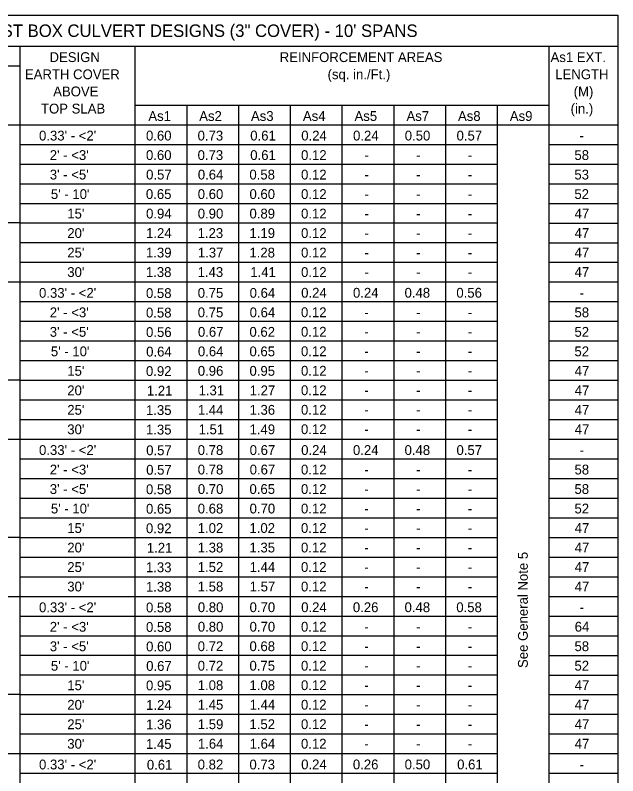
# Model space of a CAD drawing. Extents: x 10351.18 to 10353.4, y 76371.55 to 76372.62.
# Drawn here: x 10351.4001 to 10351.7867, y 76372.0471 to 76372.5347 of the extents above; entities that cross this region are included whole.
import ezdxf

# ---------------------------------------------------------------- set-up
doc = ezdxf.new("R2010")
doc.units = 0
doc.layers.add('AdhocPoint_dp', color=7, linetype='Continuous')
doc.layers.add('PlotBorder_dp', color=7, linetype='Continuous')

msp = doc.modelspace()

# ---------------------------------------------------------------- linework, layer by layer
at = {"layer": 'PlotBorder_dp'}
for p, q in [((10351.19191, 76372.53475), (10351.78665, 76372.53475)), ((10351.78665, 76372.53475), (10351.78665, 76371.85973)), ((10351.19191, 76372.51488), (10351.78665, 76372.51488)), ((10351.40299, 76372.51488), (10351.40299, 76371.85973)), ((10351.47687, 76372.51488), (10351.47687, 76371.85973)), ((10351.74246, 76372.51488), (10351.74246, 76371.85973)), ((10351.26055, 76372.50228), (10351.40299, 76372.50228)), ((10351.47687, 76372.47713), (10351.74246, 76372.47713)), ((10351.51007, 76372.47713), (10351.51007, 76371.85973)), ((10351.54327, 76372.47713), (10351.54327, 76371.85973)), ((10351.57647, 76372.47713), (10351.57647, 76371.85973)), ((10351.60967, 76372.47713), (10351.60967, 76371.85973)), ((10351.64287, 76372.47713), (10351.64287, 76371.85973)), ((10351.64287, 76372.47713), (10351.64287, 76371.85973)), ((10351.67606, 76372.47713), (10351.67606, 76371.85973)), ((10351.70926, 76372.47713), (10351.70926, 76371.85973)), ((10351.19191, 76372.46453), (10351.78665, 76372.46453)), ((10351.40299, 76372.45193), (10351.70926, 76372.45193)), ((10351.74246, 76372.45191), (10351.78665, 76372.45191)), ((10351.40299, 76372.43933), (10351.70926, 76372.43933)), ((10351.74246, 76372.43931), (10351.78665, 76372.43931)), ((10351.40299, 76372.42673), (10351.70926, 76372.42673)), ((10351.74246, 76372.42671), (10351.78665, 76372.42671)), ((10351.40299, 76372.41413), (10351.70926, 76372.41413)), ((10351.74246, 76372.41411), (10351.78665, 76372.41411)), ((10351.40299, 76372.40153), (10351.26055, 76372.40153)), ((10351.40299, 76372.40153), (10351.70926, 76372.40153)), ((10351.74246, 76372.40151), (10351.78665, 76372.40151)), ((10351.40299, 76372.38893), (10351.70926, 76372.38893)), ((10351.74246, 76372.38891), (10351.78665, 76372.38891)), ((10351.40299, 76372.37633), (10351.70926, 76372.37633)), ((10351.74246, 76372.37631), (10351.78665, 76372.37631)), ((10351.19191, 76372.36373), (10351.70926, 76372.36373)), ((10351.40362, 76372.36371), (10351.4758, 76372.36371)), ((10351.74246, 76372.36371), (10351.78665, 76372.36371)), ((10351.40299, 76372.35113), (10351.70926, 76372.35113)), ((10351.74246, 76372.35111), (10351.78665, 76372.35111)), ((10351.40299, 76372.33853), (10351.70926, 76372.33853)), ((10351.74246, 76372.33851), (10351.78665, 76372.33851)), ((10351.40299, 76372.32593), (10351.70926, 76372.32593)), ((10351.74246, 76372.32591), (10351.78665, 76372.32591)), ((10351.40299, 76372.31333), (10351.70926, 76372.31333)), ((10351.74246, 76372.31331), (10351.78665, 76372.31331)), ((10351.40299, 76372.30073), (10351.26055, 76372.30073)), ((10351.40299, 76372.30073), (10351.70926, 76372.30073)), ((10351.74246, 76372.30071), (10351.78665, 76372.30071)), ((10351.40299, 76372.28813), (10351.70926, 76372.28813)), ((10351.74246, 76372.28811), (10351.78665, 76372.28811)), ((10351.40299, 76372.27553), (10351.70926, 76372.27553)), ((10351.40362, 76372.27551), (10351.4758, 76372.27551)), ((10351.74246, 76372.27551), (10351.78665, 76372.27551)), ((10351.19191, 76372.26293), (10351.70926, 76372.26293)), ((10351.74246, 76372.26291), (10351.78665, 76372.26291)), ((10351.40299, 76372.25033), (10351.70926, 76372.25033)), ((10351.74246, 76372.25031), (10351.78665, 76372.25031)), ((10351.40299, 76372.23773), (10351.70926, 76372.23773)), ((10351.74246, 76372.23771), (10351.78665, 76372.23771)), ((10351.40299, 76372.22513), (10351.70926, 76372.22513)), ((10351.74246, 76372.22511), (10351.78665, 76372.22511)), ((10351.40299, 76372.21253), (10351.70926, 76372.21253)), ((10351.74246, 76372.21251), (10351.78665, 76372.21251)), ((10351.40299, 76372.19993), (10351.26055, 76372.19993)), ((10351.40299, 76372.19993), (10351.70926, 76372.19993)), ((10351.74246, 76372.19991), (10351.78665, 76372.19991)), ((10351.40299, 76372.18733), (10351.70926, 76372.18733)), ((10351.74246, 76372.18731), (10351.78665, 76372.18731)), ((10351.40299, 76372.17473), (10351.70926, 76372.17473)), ((10351.74246, 76372.17471), (10351.78665, 76372.17471)), ((10351.19191, 76372.16213), (10351.70926, 76372.16213)), ((10351.40362, 76372.16211), (10351.4758, 76372.16211)), ((10351.74246, 76372.16211), (10351.78665, 76372.16211)), ((10351.40299, 76372.14953), (10351.70926, 76372.14953)), ((10351.74246, 76372.14951), (10351.78665, 76372.14951)), ((10351.40299, 76372.13693), (10351.70926, 76372.13693)), ((10351.74246, 76372.13691), (10351.78665, 76372.13691)), ((10351.40299, 76372.12433), (10351.70926, 76372.12433)), ((10351.74246, 76372.12431), (10351.78665, 76372.12431)), ((10351.40299, 76372.11173), (10351.70926, 76372.11173)), ((10351.74246, 76372.11171), (10351.78665, 76372.11171)), ((10351.40299, 76372.09913), (10351.26055, 76372.09913)), ((10351.40299, 76372.09913), (10351.70926, 76372.09913)), ((10351.74246, 76372.09911), (10351.78665, 76372.09911)), ((10351.40299, 76372.08653), (10351.70926, 76372.08653)), ((10351.74246, 76372.08651), (10351.78665, 76372.08651)), ((10351.40299, 76372.07393), (10351.70926, 76372.07393)), ((10351.74246, 76372.07391), (10351.78665, 76372.07391)), ((10351.19191, 76372.06133), (10351.70926, 76372.06133)), ((10351.40362, 76372.06131), (10351.4758, 76372.06131)), ((10351.74246, 76372.06131), (10351.78665, 76372.06131)), ((10351.40299, 76372.04873), (10351.70926, 76372.04873)), ((10351.74246, 76372.04871), (10351.78665, 76372.04871))]:
    msp.add_line(p, q, dxfattribs=at)

# ---------------------------------------------------------------- texts
at = {"layer": 'AdhocPoint_dp'}
for s, height, p in [('TABLE 14 - STANDARD PRECAST BOX CULVERT DESIGNS (3" COVER) - 10\' SPANS', 0.008, (10351.23445, 76372.52081)), ('As1', 0.0063, (10351.48549, 76372.46696)), ('As2', 0.0063, (10351.51812, 76372.46696)), ('As3', 0.0063, (10351.55132, 76372.46696)), ('As4', 0.0063, (10351.58465, 76372.46696)), ('As5', 0.0063, (10351.61775, 76372.46696)), ('As7', 0.0063, (10351.65109, 76372.46696)), ('As8', 0.0063, (10351.68413, 76372.46696)), ('As9', 0.0063, (10351.71738, 76372.46696))]:
    msp.add_text(s, height=height, dxfattribs=at).set_placement(p)
msp.add_text('See General Note 5', height=0.0063, rotation=90, dxfattribs=at).set_placement((10351.72891, 76372.11621))
at = {"layer": 'PlotBorder_dp'}
for s, p in [('DESIGN', (10351.42209, 76372.50472)), ('REINFORCEMENT AREAS', (10351.56977, 76372.50472)), ('EARTH COVER', (10351.4063, 76372.49372)), ('(sq. in./Ft.)', (10351.60047, 76372.49372)), ('ABOVE', (10351.42444, 76372.48272)), ('TOP SLAB', (10351.41661, 76372.47172)), ("0.33' - <2'", (10351.41535, 76372.45441)), ('0.60', (10351.48397, 76372.45441)), ('0.73', (10351.51709, 76372.45441)), ('0.61', (10351.55086, 76372.45441)), ('0.24', (10351.58358, 76372.45441)), ('0.24', (10351.61681, 76372.45441)), ('0.50', (10351.64997, 76372.45441)), ('0.57', (10351.68322, 76372.45441)), ("2' - <3'", (10351.42225, 76372.44191)), ('0.60', (10351.48397, 76372.44191)), ('0.73', (10351.51709, 76372.44191)), ('0.61', (10351.55086, 76372.44191)), ('0.12', (10351.58345, 76372.44191)), ('-', (10351.62409, 76372.44191)), ('-', (10351.6573, 76372.44191)), ('-', (10351.69048, 76372.44191)), ("3' - <5'", (10351.42225, 76372.42941)), ('0.57', (10351.48404, 76372.42941)), ('0.64', (10351.51722, 76372.42941)), ('0.58', (10351.55031, 76372.42941)), ('0.12', (10351.58345, 76372.42941)), ('-', (10351.62409, 76372.42941)), ('-', (10351.6573, 76372.42941)), ('-', (10351.69048, 76372.42941)), ("5' - 10'", (10351.42296, 76372.41691)), ('0.65', (10351.48392, 76372.41691)), ('0.60', (10351.51717, 76372.41691)), ('0.60', (10351.55037, 76372.41691)), ('0.12', (10351.58345, 76372.41691)), ('-', (10351.62409, 76372.41691)), ('-', (10351.6573, 76372.41691)), ('-', (10351.69048, 76372.41691)), ("15'", (10351.43348, 76372.40441)), ('0.94', (10351.48402, 76372.40441)), ('0.90', (10351.51717, 76372.40441)), ('0.89', (10351.55036, 76372.40441)), ('0.12', (10351.58345, 76372.40441)), ('-', (10351.62409, 76372.40441)), ('-', (10351.6573, 76372.40441)), ('-', (10351.69048, 76372.40441)), ("20'", (10351.43348, 76372.39191)), ('1.24', (10351.48402, 76372.39191)), ('1.23', (10351.51709, 76372.39191)), ('1.19', (10351.55036, 76372.39191)), ('0.12', (10351.58345, 76372.39191)), ('-', (10351.62409, 76372.39191)), ('-', (10351.6573, 76372.39191)), ('-', (10351.69048, 76372.39191)), ("25'", (10351.43348, 76372.37941)), ('1.39', (10351.48396, 76372.37941)), ('1.37', (10351.51724, 76372.37941)), ('1.28', (10351.55031, 76372.37941)), ('0.12', (10351.58345, 76372.37941)), ('-', (10351.62409, 76372.37941)), ('-', (10351.6573, 76372.37941)), ('-', (10351.69048, 76372.37941)), ("30'", (10351.43348, 76372.36691)), ('1.38', (10351.48391, 76372.36691)), ('1.43', (10351.51709, 76372.36691)), ('1.41', (10351.55086, 76372.36691)), ('0.12', (10351.58345, 76372.36691)), ('-', (10351.62409, 76372.36691)), ('-', (10351.6573, 76372.36691)), ('-', (10351.69048, 76372.36691)), ("0.33' - <2'", (10351.41535, 76372.35357)), ('0.58', (10351.48397, 76372.35342)), ('0.75', (10351.51717, 76372.35357)), ('0.64', (10351.55047, 76372.35357)), ('0.24', (10351.58352, 76372.35363)), ('0.24', (10351.61676, 76372.35363)), ('0.48', (10351.64986, 76372.35363)), ('0.56', (10351.68309, 76372.35363)), ('-', (10351.76219, 76372.35357)), ("2' - <3'", (10351.42225, 76372.34107)), ('0.58', (10351.48397, 76372.34092)), ('0.75', (10351.51717, 76372.34107)), ('0.64', (10351.55047, 76372.34107)), ('0.12', (10351.5834, 76372.34113)), ('58', (10351.75887, 76372.34107)), ('-', (10351.62403, 76372.34113)), ('-', (10351.65724, 76372.34113)), ('-', (10351.69043, 76372.34113)), ("3' - <5'", (10351.42225, 76372.32857)), ('0.56', (10351.48401, 76372.32842)), ('0.67', (10351.51729, 76372.32857)), ('0.62', (10351.55035, 76372.32857)), ('0.12', (10351.5834, 76372.32863)), ('-', (10351.62403, 76372.32863)), ('-', (10351.65724, 76372.32863)), ('-', (10351.69043, 76372.32863)), ('52', (10351.75885, 76372.32857)), ("5' - 10'", (10351.42296, 76372.31607)), ('0.64', (10351.48407, 76372.31592)), ('0.64', (10351.51727, 76372.31607)), ('0.65', (10351.55037, 76372.31607)), ('0.12', (10351.5834, 76372.31613)), ('52', (10351.75885, 76372.31607)), ('-', (10351.62403, 76372.31613)), ('-', (10351.65724, 76372.31613)), ('-', (10351.69043, 76372.31613)), ("15'", (10351.43348, 76372.30357)), ('0.92', (10351.48395, 76372.30342)), ('0.96', (10351.51721, 76372.30357)), ('0.95', (10351.55037, 76372.30357)), ('0.12', (10351.5834, 76372.30363)), ('-', (10351.62403, 76372.30363)), ('-', (10351.65724, 76372.30363)), ('-', (10351.69043, 76372.30363)), ('47', (10351.759, 76372.30357)), ("20'", (10351.43348, 76372.29107)), ('1.21', (10351.48452, 76372.29092)), ('1.31', (10351.51771, 76372.29107)), ('1.27', (10351.55049, 76372.29107)), ('0.12', (10351.5834, 76372.29113)), ('47', (10351.759, 76372.29107)), ('-', (10351.62403, 76372.29113)), ('-', (10351.65724, 76372.29113)), ('-', (10351.69043, 76372.29113)), ("25'", (10351.43348, 76372.27857)), ('1.35', (10351.48397, 76372.27842)), ('1.44', (10351.51727, 76372.27857)), ('1.36', (10351.55041, 76372.27857)), ('0.12', (10351.5834, 76372.27863)), ('47', (10351.759, 76372.27857)), ('-', (10351.62403, 76372.27863)), ('-', (10351.65724, 76372.27863)), ('-', (10351.69043, 76372.27863)), ("30'", (10351.43348, 76372.26607)), ('1.35', (10351.48397, 76372.26592)), ('1.51', (10351.51771, 76372.26607)), ('1.49', (10351.55041, 76372.26607)), ('0.12', (10351.5834, 76372.26613)), ('47', (10351.759, 76372.26607)), ('-', (10351.62403, 76372.26613)), ('-', (10351.65724, 76372.26613)), ('-', (10351.69043, 76372.26613)), ("0.33' - <2'", (10351.41535, 76372.25279)), ('0.57', (10351.48409, 76372.25264)), ('0.78', (10351.51716, 76372.25279)), ('0.67', (10351.55049, 76372.25279)), ('0.24', (10351.58352, 76372.25279)), ('0.24', (10351.61676, 76372.25279)), ('0.48', (10351.64986, 76372.25279)), ('0.57', (10351.68317, 76372.25279)), ('-', (10351.76219, 76372.25279)), ("2' - <3'", (10351.42225, 76372.24029)), ('0.57', (10351.48409, 76372.24014)), ('0.78', (10351.51716, 76372.24029)), ('0.67', (10351.55049, 76372.24029)), ('0.12', (10351.5834, 76372.24029)), ('-', (10351.62403, 76372.24029)), ('-', (10351.65724, 76372.24029)), ('-', (10351.69043, 76372.24029)), ('58', (10351.75887, 76372.24029)), ("3' - <5'", (10351.42225, 76372.22779)), ('0.58', (10351.48397, 76372.22764)), ('0.70', (10351.51722, 76372.22779)), ('0.65', (10351.55037, 76372.22779)), ('0.12', (10351.5834, 76372.22779)), ('58', (10351.75887, 76372.22779)), ('-', (10351.62403, 76372.22779)), ('-', (10351.65724, 76372.22779)), ('-', (10351.69043, 76372.22779)), ("5' - 10'", (10351.42296, 76372.21529)), ('0.65', (10351.48397, 76372.21514)), ('0.68', (10351.51716, 76372.21529)), ('0.70', (10351.55043, 76372.21529)), ('0.12', (10351.5834, 76372.21529)), ('52', (10351.75885, 76372.21529)), ('-', (10351.62403, 76372.21529)), ('-', (10351.65724, 76372.21529)), ('-', (10351.69043, 76372.21529)), ("15'", (10351.43348, 76372.20279)), ('0.92', (10351.48395, 76372.20264)), ('1.02', (10351.51715, 76372.20279)), ('1.02', (10351.55035, 76372.20279)), ('0.12', (10351.5834, 76372.20279)), ('47', (10351.759, 76372.20279)), ('-', (10351.62403, 76372.20279)), ('-', (10351.65724, 76372.20279)), ('-', (10351.69043, 76372.20279)), ("20'", (10351.43348, 76372.19029)), ('1.21', (10351.48452, 76372.19014)), ('1.38', (10351.51716, 76372.19029)), ('1.35', (10351.55037, 76372.19029)), ('0.12', (10351.5834, 76372.19029)), ('47', (10351.759, 76372.19029)), ('-', (10351.62403, 76372.19029)), ('-', (10351.65724, 76372.19029)), ('-', (10351.69043, 76372.19029)), ("25'", (10351.43348, 76372.17779)), ('1.52', (10351.51715, 76372.17779)), ('0.12', (10351.5834, 76372.17779)), ('1.33', (10351.48394, 76372.17764)), ('1.44', (10351.55047, 76372.17779)), ('-', (10351.62403, 76372.17779)), ('-', (10351.65724, 76372.17779)), ('-', (10351.69043, 76372.17779)), ('47', (10351.759, 76372.17779)), ("30'", (10351.43348, 76372.16529)), ('1.38', (10351.48397, 76372.16514)), ('1.58', (10351.51716, 76372.16529)), ('1.57', (10351.55049, 76372.16529)), ('0.12', (10351.5834, 76372.16529)), ('47', (10351.759, 76372.16529)), ('-', (10351.62403, 76372.16529)), ('-', (10351.65724, 76372.16529)), ('-', (10351.69043, 76372.16529)), ("0.33' - <2'", (10351.41535, 76372.15196)), ('0.58', (10351.48397, 76372.15186)), ('0.80', (10351.51722, 76372.15201)), ('0.70', (10351.55043, 76372.15201)), ('0.24', (10351.58352, 76372.15201)), ('0.26', (10351.6167, 76372.15201)), ('0.48', (10351.64986, 76372.15201)), ('0.58', (10351.68304, 76372.15201)), ('-', (10351.76219, 76372.15201)), ("2' - <3'", (10351.42225, 76372.13946)), ('0.58', (10351.48397, 76372.13936)), ('0.80', (10351.51722, 76372.13951)), ('0.70', (10351.55043, 76372.13951)), ('0.12', (10351.5834, 76372.13951)), ('64', (10351.75898, 76372.13951)), ('-', (10351.62403, 76372.13951)), ('-', (10351.65724, 76372.13951)), ('-', (10351.69043, 76372.13951)), ("3' - <5'", (10351.42225, 76372.12696)), ('0.60', (10351.48403, 76372.12686)), ('0.72', (10351.51715, 76372.12701)), ('0.68', (10351.55037, 76372.12701)), ('0.12', (10351.5834, 76372.12701)), ('58', (10351.75887, 76372.12701)), ('-', (10351.62403, 76372.12701)), ('-', (10351.65724, 76372.12701)), ('-', (10351.69043, 76372.12701)), ("5' - 10'", (10351.42296, 76372.11446)), ('0.72', (10351.51715, 76372.11451)), ('0.75', (10351.55037, 76372.11451)), ('0.12', (10351.5834, 76372.11451)), ('52', (10351.75885, 76372.11451)), ('0.67', (10351.48409, 76372.11436)), ('-', (10351.62403, 76372.11451)), ('-', (10351.65724, 76372.11451)), ('-', (10351.69043, 76372.11451)), ("15'", (10351.43348, 76372.10196)), ('0.95', (10351.48397, 76372.10186)), ('1.08', (10351.51716, 76372.10201)), ('1.08', (10351.55037, 76372.10201)), ('0.12', (10351.5834, 76372.10201)), ('47', (10351.759, 76372.10201)), ('-', (10351.62403, 76372.10201)), ('-', (10351.65724, 76372.10201)), ('-', (10351.69043, 76372.10201)), ("20'", (10351.43348, 76372.08946)), ('1.24', (10351.48407, 76372.08936)), ('1.45', (10351.51717, 76372.08951)), ('1.44', (10351.55047, 76372.08951)), ('0.12', (10351.5834, 76372.08951)), ('-', (10351.62403, 76372.08951)), ('-', (10351.65724, 76372.08951)), ('-', (10351.69043, 76372.08951)), ('47', (10351.759, 76372.08951)), ("25'", (10351.43348, 76372.07696)), ('1.36', (10351.48401, 76372.07686)), ('1.59', (10351.51721, 76372.07701)), ('1.52', (10351.55035, 76372.07701)), ('0.12', (10351.5834, 76372.07701)), ('47', (10351.759, 76372.07701)), ('-', (10351.62403, 76372.07701)), ('-', (10351.65724, 76372.07701)), ('-', (10351.69043, 76372.07701)), ("30'", (10351.43348, 76372.06446)), ('1.45', (10351.48397, 76372.06436)), ('1.64', (10351.51727, 76372.06451)), ('1.64', (10351.55047, 76372.06451)), ('0.12', (10351.5834, 76372.06451)), ('-', (10351.62403, 76372.06451)), ('-', (10351.65724, 76372.06451)), ('-', (10351.69043, 76372.06451)), ('47', (10351.759, 76372.06451)), ("0.33' - <2'", (10351.41535, 76372.05118)), ('0.61', (10351.48452, 76372.05102)), ('0.82', (10351.51715, 76372.05118)), ('0.73', (10351.55034, 76372.05118)), ('0.24', (10351.58352, 76372.05123)), ('0.26', (10351.6167, 76372.05123)), ('0.50', (10351.64992, 76372.05123)), ('0.61', (10351.68359, 76372.05123)), ('-', (10351.76219, 76372.05118))]:
    msp.add_text(s, height=0.0063, dxfattribs=at).set_placement(p)
for s, p in [('As1 EXT.', (10351.74351, 76372.50472)), ('LENGTH', (10351.74653, 76372.49372)), ('(M)', (10351.75834, 76372.48272)), ('(in.)', (10351.75638, 76372.47172)), ('-', (10351.76213, 76372.45441)), ('58', (10351.75882, 76372.44191)), ('53', (10351.7588, 76372.42941)), ('52', (10351.7588, 76372.41691)), ('47', (10351.75894, 76372.40441)), ('47', (10351.75894, 76372.39191)), ('47', (10351.75894, 76372.37941)), ('47', (10351.75894, 76372.36691))]:
    msp.add_text(s, height=0.0063, rotation=360, dxfattribs=at).set_placement(p)

doc.saveas('drawing.dxf')
